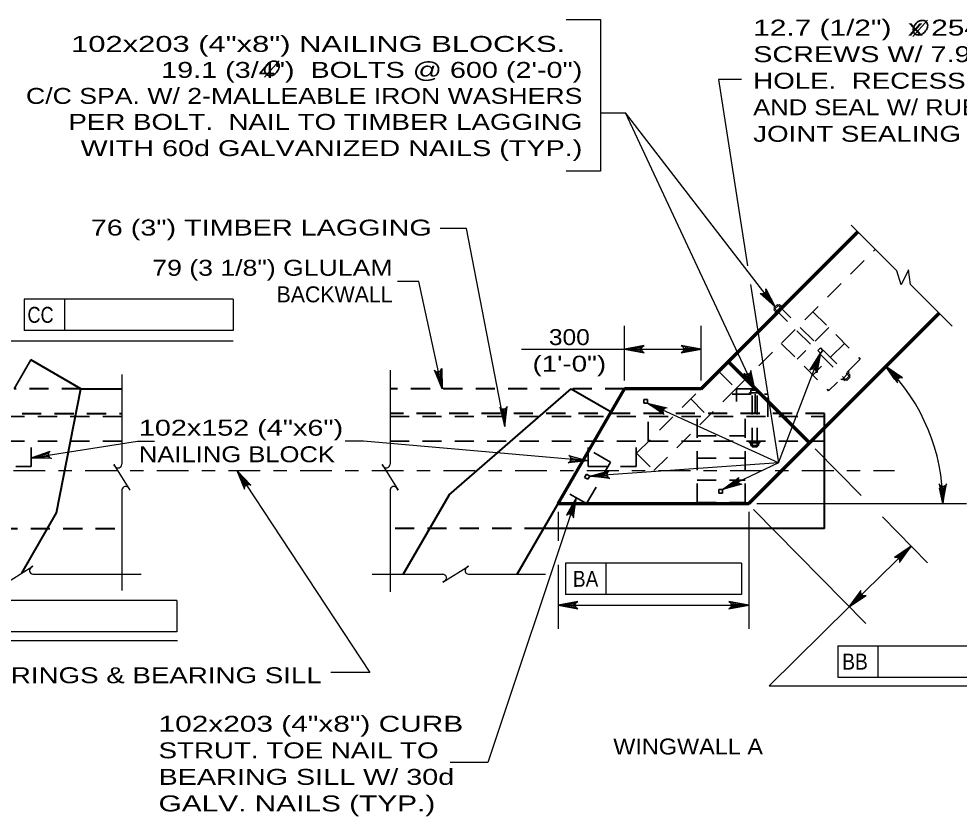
# Model space of a CAD drawing. Extents: x -6.4 to 73.1, y -66 to 0.
# Drawn here: x 57.8 to 64.89, y -57.54 to -51.53 of the extents above; entities that cross this region are included whole.
import ezdxf
from ezdxf.enums import TextEntityAlignment as Align

# ---------------------------------------------------------------- set-up
doc = ezdxf.new("R2010")
doc.units = 0
doc.header["$LTSCALE"] = 0.048
doc.linetypes.add('DOT_DASHED', pattern=[7.7, 5, -1.2, 0.3, -1.2])
doc.linetypes.add('MEDIUM_DASHED', pattern=[4.5, 3, -1.5])
for name, color, linetype, lineweight in [('3', 7, 'Continuous', 35), ('4', 7, 'Continuous', 25), ('5', 7, 'Continuous', 25), ('52', 7, 'Continuous', 25), ('8', 7, 'Continuous', 25)]:
    doc.layers.add(name, color=color, linetype=linetype, lineweight=lineweight)

msp = doc.modelspace()

# ---------------------------------------------------------------- hatches: boundary and pattern name
at = {"layer": '4'}
for points in [[(62.48167, -53.99817), (62.48167, -54.0375), (62.36358, -54.01783)], [(62.823, -53.99817), (62.823, -54.0375), (62.94108, -54.01783)], [(64.42892, -54.21992), (64.39992, -54.24667), (64.33433, -54.1465)], [(63.34942, -54.32542), (63.29292, -54.22117), (63.311, -54.21325)], [(61.46417, -54.59975), (61.44558, -54.48275), (61.46517, -54.48125)], [(59.44375, -54.93242), (59.51692, -55.02567), (59.5005, -55.0365)], [(64.73842, -55.06375), (64.77775, -55.06217), (64.76283, -55.18092)], [(62.00092, -55.13625), (61.97275, -55.25142), (61.95408, -55.24517)], [(64.42525, -55.56983), (64.45292, -55.59792), (64.52325, -55.501)], [(64.12842, -55.86192), (64.156, -55.89), (64.05808, -55.95883)], [(61.98158, -55.92608), (61.98158, -55.9655), (61.8635, -55.94575)], [(63.18175, -55.92608), (63.18175, -55.9655), (63.29983, -55.94575)]]:
    msp.add_hatch(color=256, dxfattribs=at).paths.add_polyline_path(points)

# ---------------------------------------------------------------- linework, layer by layer
at = {"layer": '3', "lineweight": 25}
for p, q in [((64.07083, -53.08242), (64.41525, -53.42675)), ((64.51775, -53.52925), (64.50475, -53.41992)), ((64.51775, -53.52925), (64.83283, -53.84442))]:
    msp.add_line(p, q, dxfattribs=at)
at = {"layer": '3', "lineweight": 70}
for p, q in [((62.94108, -54.31483), (64.12217, -53.13375)), ((63.29983, -55.18092), (64.73467, -53.74617)), ((63.14525, -54.11067), (63.75767, -54.72308)), ((61.8635, -55.18092), (62.36358, -54.31483)), ((62.94108, -54.31483), (62.36358, -54.31483)), ((61.8635, -55.18092), (63.29983, -55.18092))]:
    msp.add_line(p, q, dxfattribs=at)
at = {"layer": '3', "linetype": 'MEDIUM_DASHED'}
for p, q in [((63.20417, -54.31483), (64.25375, -53.26525)), ((63.51608, -53.68017), (63.49, -53.70625)), ((63.531, -53.68017), (63.49, -53.72117)), ((63.55333, -53.68767), (63.4975, -53.7435)), ((63.51608, -53.68017), (64.06425, -54.22833)), ((63.531, -53.68017), (63.54592, -53.69508)), ((63.55333, -53.68767), (63.56083, -53.69508)), ((63.49, -53.70625), (64.03817, -54.25442)), ((63.49, -53.72117), (63.50492, -53.73608)), ((63.4975, -53.7435), (63.50492, -53.751)), ((63.78367, -53.73533), (64.14067, -54.09233)), ((63.90292, -53.85458), (63.66442, -54.09308)), ((63.54517, -53.97383), (63.90217, -54.33083)), ((64.02183, -53.97342), (63.78325, -54.212)), ((64.14067, -54.09233), (63.90217, -54.33083)), ((63.07267, -54.18325), (63.20583, -54.31642)), ((64.05683, -54.19108), (64.00092, -54.247)), ((64.05683, -54.19108), (64.04933, -54.18367)), ((64.00092, -54.247), (63.9935, -54.2395)), ((64.02325, -54.25442), (64.00833, -54.2395)), ((64.06425, -54.21342), (64.02325, -54.25442)), ((64.06425, -54.22833), (64.03817, -54.25442)), ((64.06425, -54.21342), (64.04933, -54.1985)), ((62.455, -54.80092), (62.94108, -54.31483)), ((62.5865, -54.93242), (63.20417, -54.31483)), ((63.34942, -54.31483), (63.20417, -54.31483)), ((63.208, -54.41083), (63.208, -54.311)), ((63.31633, -54.32542), (63.37425, -54.32542)), ((63.31633, -54.32542), (63.31633, -54.3465)), ((63.32683, -54.31483), (63.36375, -54.31483)), ((63.32683, -54.75392), (63.32683, -54.31483)), ((63.34942, -54.50083), (63.34942, -54.31483)), ((63.36375, -54.75392), (63.36375, -54.31483)), ((63.37425, -54.32542), (63.37425, -54.3465)), ((62.86375, -54.39217), (62.997, -54.52533)), ((63.1755, -54.357), (63.444, -54.357)), ((63.30575, -54.3465), (63.38483, -54.3465)), ((63.30575, -54.3465), (63.30575, -54.357)), ((63.38483, -54.3465), (63.38483, -54.357)), ((63.444, -54.52567), (63.444, -54.357)), ((58.57767, -54.52367), (56.11933, -54.52367)), ((60.59825, -54.52367), (63.87075, -54.52367)), ((62.54283, -54.70967), (62.54283, -54.52367)), ((62.91142, -55.17325), (62.91142, -54.50083)), ((63.27233, -55.17325), (63.27233, -54.50083)), ((62.91142, -54.66892), (63.27233, -54.66892)), ((58.57767, -54.70967), (56.11933, -54.70967)), ((57.89592, -54.90208), (57.89592, -54.70967)), ((60.59825, -54.70967), (63.87075, -54.70967)), ((62.0905, -54.90208), (62.0905, -54.70967)), ((62.45133, -54.90208), (62.45133, -54.70967)), ((63.30575, -54.72225), (63.30575, -54.71175)), ((63.30575, -54.72225), (63.38483, -54.72225)), ((63.31633, -54.74333), (63.31633, -54.72225)), ((63.31633, -54.74333), (63.37425, -54.74333)), ((63.32683, -54.75392), (63.36375, -54.75392)), ((63.37425, -54.74333), (63.37425, -54.72225)), ((63.38483, -54.72225), (63.38483, -54.71175)), ((62.25875, -54.86842), (62.09767, -54.77542)), ((62.455, -54.80092), (62.5865, -54.93242)), ((62.07825, -55.18092), (62.25875, -54.86842)), ((62.91142, -54.83708), (63.27233, -54.83708)), ((57.535, -54.90208), (57.89592, -54.90208)), ((62.0905, -54.90208), (62.45133, -54.90208)), ((62.91142, -55.00517), (63.27233, -55.00517)), ((62.07825, -55.18092), (61.91717, -55.08792)), ((62.91142, -55.17325), (63.27233, -55.17325))]:
    msp.add_line(p, q, dxfattribs=at)
at = {"layer": '3'}
msp.add_line((57.89317, -54.09775), (57.76783, -54.31483), dxfattribs=at)
at = {"layer": '3', "lineweight": 40}
for p, q in [((58.269, -54.31483), (57.89317, -54.09775)), ((58.08683, -55.25042), (58.269, -54.31483)), ((58.269, -54.31483), (58.57767, -54.31483)), ((61.04308, -55.11367), (61.962, -54.31483)), ((61.962, -54.31483), (62.26317, -54.48867)), ((63.87075, -55.3675), (63.87075, -54.50083)), ((61.04308, -55.11367), (60.69725, -55.71275)), ((61.55642, -55.71275), (61.8635, -55.18092)), ((57.82425, -55.70517), (58.08683, -55.25042)), ((63.87075, -55.367), (61.75608, -55.367))]:
    msp.add_line(p, q, dxfattribs=at)
at = {"layer": '3', "linetype": 'MEDIUM_DASHED', "lineweight": 40}
for p, q in [((58.269, -54.31483), (57.76783, -54.31483)), ((62.36358, -54.31483), (60.59825, -54.31483)), ((56.11933, -54.50083), (58.57767, -54.50083)), ((63.87075, -54.50083), (60.59825, -54.50083)), ((61.75608, -55.367), (60.59825, -55.367))]:
    msp.add_line(p, q, dxfattribs=at)
at = {"layer": '3', "linetype": 'DOT_DASHED', "lineweight": 25}
msp.add_line((55.6005, -54.93242), (64.39775, -54.93242), dxfattribs=at)
at = {"layer": '3', "lineweight": 25}
msp.add_lwpolyline([(64.50475, -53.41992), (64.4485, -53.53233), (64.41525, -53.42675)], dxfattribs=at)
at = {"layer": '3', "linetype": 'MEDIUM_DASHED'}
for points in [[(63.83992, -54.04708), (63.85967, -54.02733), (63.83992, -54.00767), (63.82017, -54.02733)], [(62.50975, -54.42317), (62.53767, -54.42317), (62.53767, -54.39525), (62.50975, -54.39525)], [(62.08833, -54.997), (62.10225, -54.97283), (62.07808, -54.95892), (62.06417, -54.98308)], [(63.074, -55.10125), (63.10192, -55.10125), (63.10192, -55.07333), (63.074, -55.07333)]]:
    msp.add_lwpolyline(points, close=True, dxfattribs=at)
at = {"layer": '4'}
for p, q in [((61.92417, -51.53383), (62.18308, -51.53383)), ((63.24475, -51.98442), (63.07275, -51.98442)), ((63.07275, -51.98442), (63.29175, -53.38892)), ((62.18308, -52.23692), (62.37208, -52.23692)), ((63.49858, -53.69767), (62.37208, -52.23692)), ((63.34942, -54.32542), (62.37208, -52.23692)), ((61.17425, -53.10875), (60.97658, -53.10875)), ((61.46417, -54.59975), (61.17417, -53.10867)), ((63.31383, -53.53017), (63.52333, -54.87367)), ((59.41725, -53.64067), (57.84242, -53.64067)), ((57.84242, -53.64067), (57.84242, -53.87692)), ((58.14492, -53.64067), (58.14492, -53.87692)), ((59.41725, -53.64067), (59.41725, -53.87692)), ((59.41725, -53.87692), (57.84242, -53.87692)), ((62.36358, -54.25325), (62.36358, -53.84067)), ((62.94108, -54.25325), (62.94108, -53.84067)), ((57.049, -53.95325), (59.41708, -53.95325)), ((61.58917, -54.01783), (62.94108, -54.01783)), ((63.52333, -54.87367), (63.84, -54.04708)), ((63.52333, -54.87367), (62.53775, -54.42317)), ((63.80092, -54.76708), (64.14725, -55.11892)), ((63.52333, -54.87367), (62.10233, -54.97283)), ((63.52333, -54.87367), (63.102, -55.07333)), ((62.00092, -55.13625), (61.33375, -57.13125)), ((63.36142, -55.18092), (64.94, -55.18092)), ((61.86358, -55.24258), (61.86358, -55.4605)), ((63.29983, -55.2425), (63.29983, -56.12292)), ((63.33567, -55.22475), (64.18233, -56.08508)), ((64.30675, -55.28092), (64.64758, -55.62733)), ((64.52325, -55.501), (64.05808, -55.95883)), ((61.86358, -55.64233), (61.86358, -56.123)), ((63.2455, -55.62958), (61.92092, -55.62958)), ((61.92092, -55.62958), (61.92092, -55.86583)), ((62.22333, -55.62958), (62.22333, -55.86583)), ((63.2455, -55.62958), (63.2455, -55.86583)), ((63.2455, -55.86583), (61.92092, -55.86583)), ((58.99208, -55.9115), (57.41725, -55.9115)), ((58.99208, -55.9115), (58.99208, -56.14775)), ((61.8635, -55.94575), (63.29983, -55.94575)), ((64.05808, -55.95883), (63.453, -56.55425)), ((58.99208, -56.14775), (57.41725, -56.14775)), ((57.26775, -56.21242), (58.99725, -56.21242)), ((63.97042, -56.25308), (65.54517, -56.25317)), ((64.27283, -56.25317), (64.27283, -56.48933)), ((63.45308, -56.55433), (65.65033, -56.55433)), ((61.33383, -57.13125), (61.05133, -57.13125))]:
    msp.add_line(p, q, dxfattribs=at)
at = {"layer": '4', "linetype": 'MEDIUM_DASHED', "lineweight": 40}
msp.add_line((57.16033, -55.367), (58.57767, -55.367), dxfattribs=at)
at = {"layer": '4'}
for points in [[(62.18308, -51.53383), (62.18308, -52.67725), (61.92417, -52.67725)], [(60.99175, -54.31483), (60.81475, -53.50708), (60.65483, -53.50708)], [(63.49858, -53.69767), (63.38542, -53.59667), (63.39208, -53.59875), (63.39875, -53.60092), (63.4045, -53.60017), (63.41025, -53.5995), (63.41475, -53.59708), (63.41925, -53.59475), (63.42267, -53.591), (63.42608, -53.58725), (63.42825, -53.58183), (63.43042, -53.5765), (63.43008, -53.5695), (63.42967, -53.5625), (63.49858, -53.69767), (63.43008, -53.5695), (63.43042, -53.5765), (63.49858, -53.69767), (63.42825, -53.58183), (63.42608, -53.58725), (63.49858, -53.69767), (63.42267, -53.591), (63.41925, -53.59475), (63.49858, -53.69767), (63.41475, -53.59708), (63.41025, -53.5995), (63.49858, -53.69767), (63.4045, -53.60017), (63.39875, -53.60092), (63.49858, -53.69767), (63.39208, -53.59875)], [(62.36358, -54.01783), (62.51275, -54.04583), (62.50125, -54.03783), (62.49533, -54.02783), (62.49358, -54.01783), (62.49533, -54.00783), (62.50125, -53.99783), (62.51275, -53.98983), (62.36358, -54.01783), (62.50125, -53.99783), (62.49533, -54.00783), (62.36358, -54.01783), (62.49358, -54.01783), (62.49533, -54.02783), (62.36358, -54.01783), (62.50125, -54.03783)], [(62.94108, -54.01783), (62.79192, -53.98983), (62.80342, -53.99783), (62.80933, -54.00783), (62.81108, -54.01783), (62.80933, -54.02783), (62.80342, -54.03783), (62.79192, -54.04583), (62.94108, -54.01783), (62.80342, -54.03783), (62.80933, -54.02783), (62.94108, -54.01783), (62.81108, -54.01783), (62.80933, -54.00783), (62.94108, -54.01783), (62.80342, -53.99783)], [(63.83992, -54.04708), (63.81267, -54.19633), (63.80933, -54.18275), (63.80217, -54.17367), (63.79342, -54.1685), (63.78342, -54.1665), (63.772, -54.16842), (63.76042, -54.17633), (63.83992, -54.04708), (63.772, -54.16842), (63.78342, -54.1665), (63.83992, -54.04708), (63.79342, -54.1685), (63.80217, -54.17367), (63.83992, -54.04708), (63.80933, -54.18275)], [(63.34942, -54.32542), (63.31517, -54.17758), (63.31242, -54.19133), (63.30567, -54.20075), (63.29717, -54.20633), (63.28733, -54.20883), (63.27583, -54.20742), (63.26392, -54.20008), (63.34942, -54.32542), (63.27583, -54.20742), (63.28733, -54.20883), (63.34942, -54.32542), (63.29717, -54.20633), (63.30567, -54.20075), (63.34942, -54.32542), (63.31242, -54.19133)], [(64.33433, -54.1465), (64.42, -54.27167), (64.4175, -54.25792), (64.42042, -54.24667), (64.42625, -54.23842), (64.43458, -54.2325), (64.44583, -54.22967), (64.45958, -54.23217), (64.33433, -54.1465), (64.44583, -54.22967), (64.43458, -54.2325), (64.33433, -54.1465), (64.42625, -54.23842), (64.42042, -54.24667), (64.33433, -54.1465), (64.4175, -54.25792)], [(61.46417, -54.59975), (61.481, -54.44892), (61.47392, -54.461), (61.46433, -54.46767), (61.4545, -54.47008), (61.44442, -54.46917), (61.434, -54.464), (61.42517, -54.45308), (61.46417, -54.59975), (61.434, -54.464), (61.44442, -54.46917), (61.46417, -54.59975), (61.4545, -54.47008), (61.46433, -54.46767), (61.46417, -54.59975), (61.47392, -54.461)], [(62.53767, -54.42317), (62.68492, -54.45975), (62.67117, -54.46217), (62.66158, -54.46883), (62.65592, -54.47725), (62.65333, -54.487), (62.6545, -54.49858), (62.66167, -54.51058), (62.53767, -54.42317), (62.6545, -54.49858), (62.65333, -54.487), (62.53767, -54.42317), (62.65592, -54.47725), (62.66158, -54.46883), (62.53767, -54.42317), (62.67117, -54.46217)], [(57.89592, -54.83675), (58.69592, -54.71125), (58.82467, -54.71125)], [(62.0905, -54.85842), (60.39775, -54.71125), (60.26033, -54.71125)], [(59.44375, -54.93242), (60.44575, -56.45383), (60.15258, -56.45383)], [(59.44375, -54.93242), (59.50242, -55.07233), (59.50275, -55.05833), (59.50783, -55.04792), (59.51525, -55.041), (59.52458, -55.03692), (59.53617, -55.03633), (59.54917, -55.04158), (59.44375, -54.93242), (59.53617, -55.03633), (59.52458, -55.03692), (59.44375, -54.93242), (59.51525, -55.041), (59.50783, -55.04792), (59.44375, -54.93242), (59.50275, -55.05833)], [(62.10225, -54.97283), (62.24908, -54.93458), (62.23817, -54.94333), (62.23292, -54.95367), (62.23192, -54.96375), (62.23433, -54.97367), (62.24092, -54.98317), (62.253, -54.99033), (62.10225, -54.97283), (62.24092, -54.98317), (62.23433, -54.97367), (62.10225, -54.97283), (62.23192, -54.96375), (62.23292, -54.95367), (62.10225, -54.97283), (62.23817, -54.94333)], [(63.10192, -55.07333), (63.22467, -54.98417), (63.21775, -54.99633), (63.21667, -55.00792), (63.21942, -55.01767), (63.22525, -55.026), (63.23483, -55.0325), (63.24867, -55.03475), (63.10192, -55.07333), (63.23483, -55.0325), (63.22525, -55.026), (63.10192, -55.07333), (63.21942, -55.01767), (63.21667, -55.00792), (63.10192, -55.07333), (63.21775, -54.99633)], [(64.76283, -55.18092), (64.79075, -55.03175), (64.78283, -55.04325), (64.77283, -55.04917), (64.76283, -55.05092), (64.75283, -55.04917), (64.74283, -55.04325), (64.73483, -55.03175), (64.76283, -55.18092), (64.74283, -55.04325), (64.75283, -55.04917), (64.76283, -55.18092), (64.76283, -55.05092), (64.77283, -55.04917), (64.76283, -55.18092), (64.78283, -55.04325)], [(62.00092, -55.13625), (61.92708, -55.26883), (61.93833, -55.26042), (61.94967, -55.258), (61.95967, -55.2595), (61.96867, -55.26433), (61.97625, -55.27317), (61.98017, -55.28658), (62.00092, -55.13625), (61.97625, -55.27317), (61.96867, -55.26433), (62.00092, -55.13625), (61.95967, -55.2595), (61.94967, -55.258), (62.00092, -55.13625), (61.93833, -55.26042)], [(64.52325, -55.501), (64.39733, -55.58567), (64.41108, -55.58333), (64.42233, -55.58625), (64.43058, -55.59217), (64.43642, -55.6005), (64.43917, -55.61183), (64.43658, -55.6255), (64.52325, -55.501), (64.43917, -55.61183), (64.43642, -55.6005), (64.52325, -55.501), (64.43058, -55.59217), (64.42233, -55.58625), (64.52325, -55.501), (64.41108, -55.58333)], [(64.05808, -55.95883), (64.184, -55.87417), (64.17025, -55.8765), (64.159, -55.87358), (64.15075, -55.86767), (64.14492, -55.85933), (64.14217, -55.848), (64.14475, -55.83433), (64.05808, -55.95883), (64.14217, -55.848), (64.14492, -55.85933), (64.05808, -55.95883), (64.15075, -55.86767), (64.159, -55.87358), (64.05808, -55.95883), (64.17025, -55.8765)], [(61.8635, -55.94575), (62.01267, -55.97375), (62.00117, -55.96575), (61.99525, -55.95575), (61.9935, -55.94575), (61.99525, -55.93575), (62.00117, -55.92575), (62.01267, -55.91775), (61.8635, -55.94575), (62.00117, -55.92575), (61.99525, -55.93575), (61.8635, -55.94575), (61.9935, -55.94575), (61.99525, -55.95575), (61.8635, -55.94575), (62.00117, -55.96575)], [(63.29983, -55.94575), (63.15067, -55.91775), (63.16217, -55.92575), (63.16808, -55.93575), (63.16983, -55.94575), (63.16808, -55.95575), (63.16217, -55.96575), (63.15067, -55.97375), (63.29983, -55.94575), (63.16217, -55.96575), (63.16808, -55.95575), (63.29983, -55.94575), (63.16983, -55.94575), (63.16808, -55.93575), (63.29983, -55.94575), (63.16217, -55.92575)], [(63.97042, -56.25308), (63.97042, -56.48933), (65.54517, -56.48933)]]:
    msp.add_lwpolyline(points, dxfattribs=at)
for points in [[(62.48167, -53.99817), (62.48167, -54.0375), (62.36358, -54.01783)], [(62.823, -53.99817), (62.823, -54.0375), (62.94108, -54.01783)], [(64.42892, -54.21992), (64.39992, -54.24667), (64.33433, -54.1465)], [(63.34942, -54.32542), (63.29292, -54.22117), (63.311, -54.21325)], [(61.46417, -54.59975), (61.44558, -54.48275), (61.46517, -54.48125)], [(59.44375, -54.93242), (59.51692, -55.02567), (59.5005, -55.0365)], [(64.73842, -55.06375), (64.77775, -55.06217), (64.76283, -55.18092)], [(62.00092, -55.13625), (61.97275, -55.25142), (61.95408, -55.24517)], [(64.42525, -55.56983), (64.45292, -55.59792), (64.52325, -55.501)], [(64.12842, -55.86192), (64.156, -55.89), (64.05808, -55.95883)], [(61.98158, -55.92608), (61.98158, -55.9655), (61.8635, -55.94575)], [(63.18175, -55.92608), (63.18175, -55.9655), (63.29983, -55.94575)]]:
    msp.add_lwpolyline(points, close=True, dxfattribs=at)
msp.add_arc((63.29992, -55.18099), 1.46295, 0.00109, 45.00027, dxfattribs=at)
at = {"layer": '5', "lineweight": 35}
for p, q in [((64.53617, -51.66083), (64.64817, -51.53825)), ((59.65158, -51.96767), (59.76358, -51.84508))]:
    msp.add_line(p, q, dxfattribs=at)
for points in [[(64.6365, -51.55033), (64.62775, -51.5435), (64.619, -51.54108), (64.608, -51.54008), (64.60175, -51.54008), (64.591, -51.54258), (64.58117, -51.54708), (64.57425, -51.551), (64.561, -51.56158), (64.55067, -51.57508), (64.54442, -51.58775), (64.54075, -51.59933), (64.53967, -51.61008), (64.54075, -51.61933), (64.54525, -51.6325), (64.55, -51.63933), (64.55967, -51.64658), (64.57417, -51.65008), (64.59067, -51.64958), (64.6115, -51.64008), (64.62675, -51.627), (64.63825, -51.61108), (64.64575, -51.5945), (64.64825, -51.57608), (64.645, -51.56425), (64.637, -51.55033)], [(59.75192, -51.85717), (59.74317, -51.85033), (59.73442, -51.84792), (59.72342, -51.84692), (59.71717, -51.84692), (59.70642, -51.84942), (59.69658, -51.85392), (59.68967, -51.85783), (59.67642, -51.86842), (59.66608, -51.88192), (59.65983, -51.89458), (59.65617, -51.90617), (59.65508, -51.91692), (59.65617, -51.92617), (59.66067, -51.93933), (59.66542, -51.94617), (59.67508, -51.95342), (59.68958, -51.95692), (59.70608, -51.95642), (59.72692, -51.94692), (59.74217, -51.93383), (59.75367, -51.91792), (59.76117, -51.90133), (59.76367, -51.88292), (59.76042, -51.87108), (59.75242, -51.85717)]]:
    msp.add_spline(points, degree=3, dxfattribs=at)
at = {"layer": '52'}
for points in [[(60.99175, -54.31483), (60.9325, -54.17517), (60.94275, -54.18467), (60.95375, -54.18833), (60.96392, -54.18783), (60.97333, -54.184), (60.98183, -54.17608), (60.98717, -54.16317), (60.99175, -54.31483), (60.98183, -54.17608), (60.97333, -54.184), (60.99175, -54.31483), (60.96392, -54.18783), (60.95375, -54.18833), (60.99175, -54.31483), (60.94275, -54.18467)], [(57.89592, -54.83675), (58.03892, -54.786), (58.02883, -54.79567), (58.0245, -54.80642), (58.02433, -54.81658), (58.02758, -54.82625), (58.035, -54.83517), (58.04758, -54.84125), (57.89592, -54.83675), (58.035, -54.83517), (58.02758, -54.82625), (57.89592, -54.83675), (58.02433, -54.81658), (58.0245, -54.80642), (57.89592, -54.83675), (58.02883, -54.79567)], [(62.0905, -54.85842), (61.9395, -54.87333), (61.95167, -54.86642), (61.95842, -54.857), (61.961, -54.84717), (61.96017, -54.83708), (61.95508, -54.82658), (61.94433, -54.81767), (62.0905, -54.85842), (61.95508, -54.82658), (61.96017, -54.83708), (62.0905, -54.85842), (61.961, -54.84717), (61.95842, -54.857), (62.0905, -54.85842), (61.95167, -54.86642)]]:
    msp.add_lwpolyline(points, dxfattribs=at)
at = {"layer": '8'}
for p, q in [((60.59825, -54.17633), (60.59825, -54.88358)), ((58.57767, -54.20825), (58.57767, -54.88358)), ((58.57767, -55.07775), (58.57767, -55.83625)), ((60.59825, -55.07775), (60.59825, -55.84583)), ((57.90808, -55.71275), (58.72233, -55.71275)), ((60.46442, -55.71275), (60.99483, -55.71275)), ((61.18908, -55.71275), (61.77008, -55.71275))]:
    msp.add_line(p, q, dxfattribs=at)
for points in [[(58.52467, -54.89775), (58.51725, -54.88575), (58.63817, -55.07817), (58.63008, -55.06533)], [(60.54525, -54.89775), (60.53775, -54.88575), (60.65867, -55.07817), (60.65058, -55.06533)], [(57.728, -55.76575), (57.716, -55.77325), (57.90842, -55.65233), (57.89558, -55.66042)], [(61.009, -55.76575), (60.997, -55.77325), (61.1895, -55.65233), (61.17658, -55.66042)]]:
    msp.add_lwpolyline(points, dxfattribs=at)
for centre, start, end in [((58.54934, -54.88358), 210, 0), ((60.56987, -54.88358), 210, 0), ((58.60604, -55.08047), 32.13276, 174.67141), ((60.62657, -55.08047), 32.13276, 174.67141), ((57.91073, -55.68452), 122.13276, 264.67141), ((61.19175, -55.68452), 122.13276, 264.67141), ((60.99486, -55.74122), 300, 90)]:
    msp.add_arc(centre, 0.02841, start, end, dxfattribs=at)

# ---------------------------------------------------------------- texts
at = {"layer": '4', "width": 0.85}
msp.add_text('CC', height=0.12, dxfattribs=at).set_placement((57.96537, -53.81867), align=Align.CENTER)
at = {"layer": '4', "width": 0.9}
for s, rotation, p in [('BA', 0.062, (62.07152, -55.80756)), ('BB', 359.936, (64.10093, -56.43103))]:
    msp.add_text(s, height=0.12, rotation=rotation, dxfattribs=at).set_placement(p, align=Align.CENTER)
at = {"layer": '4'}
for s, width, p in [('L BEARINGS & BEARING SILL', 1.3, (57.1505, -56.53367)), ('WINGWALL A', 1.1, (62.27992, -57.07075))]:
    msp.add_text(s, height=0.12, dxfattribs=dict(at, width=width)).set_placement(p)
at = {"layer": '5'}
for s, width, p in [('12.7 (1/2")  x 254 (10") LONG LAG', 1.4, (63.33408, -51.65475)), ('SCREWS W/ 7.9 (5/16")  PILOT', 1.35, (63.33408, -51.85475)), ('HOLE.  RECESS SCREWS 25 (1")', 1.3, (63.33408, -52.05475)), ('AND SEAL W/ RUBBERIZED', 1.2, (63.33408, -52.25475)), ('JOINT SEALING MATERIAL (TYP.)', 1.3, (63.33408, -52.45475)), ('76 (3") TIMBER LAGGING', 1.35, (58.34375, -53.16133)), ('102x152 (4"x6")', 1.35, (58.70642, -54.66892)), ('NAILING BLOCK', 1.2, (58.70642, -54.86892)), ('102x203 (4"x8") CURB', 1.4, (58.85442, -56.89942)), ('STRUT. TOE NAIL TO', 1.3, (58.85442, -57.09942)), ('BEARING SILL W/ 30d', 1.35, (58.85442, -57.29942)), ('GALV. NAILS (TYP.)', 1.4, (58.85442, -57.49942))]:
    msp.add_text(s, height=0.12, dxfattribs=dict(at, width=width)).set_placement(p)
for s, width, p in [('102x203 (4"x8") NAILING BLOCKS.  ', 1.45, (62.04675, -51.77767)), ('19.1 (3/4")  BOLTS @ 600 (2\'-0")', 1.35, (62.04675, -51.97342)), ('C/C SPA. W/ 2-MALLEABLE IRON WASHERS', 1.25, (62.04675, -52.16925)), ('PER BOLT.  NAIL TO TIMBER LAGGING', 1.3, (62.04675, -52.365)), ('WITH 60d GALVANIZED NAILS (TYP.)', 1.35, (62.04675, -52.56267)), ('79 (3 1/8") GLULAM', 1.25, (60.61742, -53.46408))]:
    msp.add_text(s, height=0.12, dxfattribs=dict(at, width=width)).set_placement(p, align=Align.RIGHT)
msp.add_text('BACKWALL', height=0.12, dxfattribs=at).set_placement((60.61742, -53.66408), align=Align.RIGHT)
for s, width, p in [('300', 1.15, (61.94896, -53.98642)), ('(1\'-0")', 1.3, (61.94896, -54.18642))]:
    msp.add_text(s, height=0.12, dxfattribs=dict(at, width=width)).set_placement(p, align=Align.CENTER)

doc.saveas('drawing.dxf')
